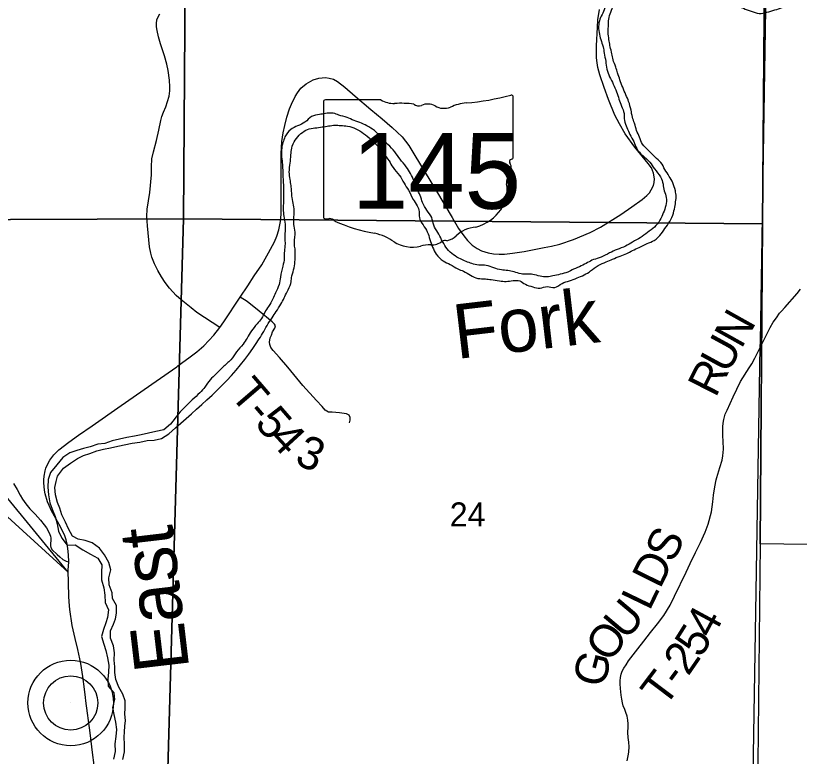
# Model space of a CAD drawing. Extents: x 0 to 34, y 0 to 22.
# Drawn here: x 5.171 to 6.533, y 17.465 to 18.753 of the extents above; entities that cross this region are included whole.
import ezdxf

# ---------------------------------------------------------------- set-up
doc = ezdxf.new("R2010")
doc.units = 0
for name, color, linetype in [('GM_X_Corporation', 7, 'Continuous'), ('GM_X_Major_River', 7, 'Continuous'), ('GM_X_Major_River_Text', 7, 'Continuous'), ('GM_X_Section_Text', 7, 'Continuous'), ('GM_X_State_Location', 7, 'Continuous'), ('GM_X_State_Route', 7, 'Continuous'), ('GM_X_State_Shield', 7, 'Continuous'), ('GM_X_Township_Road', 7, 'Continuous'), ('GM_X_Township_Road_Text', 7, 'Continuous'), ('GM_X_Township_Text', 7, 'Continuous'), ('GM_X_Unincorporated', 7, 'Continuous'), ('GM_X_Unincorporated_Location', 7, 'Continuous'), ('SH_Text', 7, 'Continuous')]:
    doc.layers.add(name, color=color, linetype=linetype)

msp = doc.modelspace()

# ---------------------------------------------------------------- linework, layer by layer
at = {"layer": 'GM_X_Corporation'}
for points in [[(5.4696, 19.395), (5.4623, 18.3997), (4.4097, 18.3961), (4.4084, 19.4053)], [(6.4758, 19.3912), (6.4726, 18.8257), (6.4692, 18.391), (5.4623, 18.3997), (5.4696, 19.395)], [(7.3418, 18.8315), (7.332, 17.8222), (6.4651, 17.8343), (6.4692, 18.391), (6.4726, 18.8257)], [(4.4097, 18.3961), (5.4623, 18.3997), (5.4343, 17.4017), (4.3969, 17.419)], [(6.4692, 18.391), (6.4651, 17.8343), (6.4606, 17.3985), (5.4343, 17.4017), (5.4623, 18.3997)]]:
    msp.add_lwpolyline(points, close=True, dxfattribs=at)
at = {"layer": 'GM_X_Major_River'}
for points in [[(5.4539, 18.0609), (5.44, 18.0428), (5.4281, 18.0331), (5.4145, 18.0302), (5.402, 18.0273), (5.3888, 18.0244), (5.3771, 18.0219), (5.3639, 18.0197), (5.3514, 18.0168), (5.3386, 18.0139), (5.3258, 18.0091), (5.3137, 18.0081), (5.3005, 18.0033), (5.2888, 18.0004), (5.2771, 17.9968), (5.2647, 17.9928), (5.2527, 17.9846), (5.2423, 17.9719), (5.2312, 17.9587), (5.2273, 17.9462), (5.2268, 17.9333), (5.2278, 17.9196), (5.2303, 17.906), (5.2344, 17.8947), (5.2395, 17.8823), (5.2428, 17.8695), (5.2453, 17.8566), (5.2509, 17.8442), (5.2606, 17.8323), (5.2742, 17.8325), (5.2877, 17.8241), (5.3007, 17.8167), (5.3137, 17.8098), (5.3204, 17.7981), (5.3203, 17.7845), (5.3202, 17.7716), (5.3239, 17.758), (5.3256, 17.7451), (5.3266, 17.7323), (5.3322, 17.7195), (5.3306, 17.7065), (5.3273, 17.697), (5.3234, 17.6852), (5.3198, 17.673), (5.3243, 17.6602), (5.3275, 17.6488), (5.3304, 17.636), (5.3326, 17.6235), (5.332, 17.6114), (5.3311, 17.5988), (5.3318, 17.5871), (5.3415, 17.5755), (5.3425, 17.5634), (5.3389, 17.5497), (5.3414, 17.5376), (5.3444, 17.5244), (5.3461, 17.5115), (5.3448, 17.4994), (5.3432, 17.4868), (5.3438, 17.4732), (5.3411, 17.4598)], [(5.357, 17.4594), (5.3598, 17.4727), (5.3599, 17.4852), (5.3593, 17.4981), (5.3602, 17.5076), (5.3608, 17.5175), (5.3617, 17.527), (5.3604, 17.538), (5.3613, 17.5494), (5.3611, 17.5611), (5.357, 17.5732), (5.35, 17.5852), (5.3452, 17.5987), (5.3434, 17.6105), (5.3432, 17.6203), (5.3422, 17.6324), (5.3428, 17.6446), (5.3406, 17.6571), (5.3358, 17.6702), (5.3356, 17.6831), (5.3406, 17.6946), (5.3446, 17.7042), (5.3463, 17.7141), (5.3461, 17.727), (5.339, 17.7393), (5.3384, 17.7492), (5.3336, 17.7631), (5.333, 17.7752), (5.3365, 17.7893), (5.3325, 17.8022), (5.325, 17.8153), (5.3164, 17.8269), (5.3038, 17.8361), (5.2915, 17.8401), (5.2794, 17.8425), (5.2698, 17.8476), (5.2627, 17.8604), (5.2576, 17.872), (5.2512, 17.8852), (5.2476, 17.8965), (5.2436, 17.9063), (5.2399, 17.9199), (5.2389, 17.9327), (5.241, 17.943), (5.2438, 17.9525), (5.2542, 17.966), (5.2662, 17.975), (5.2785, 17.9832), (5.2887, 17.9879), (5.2999, 17.9919), (5.312, 17.996), (5.3233, 17.9992), (5.3358, 18.0017), (5.3486, 18.0043), (5.3732, 18.0097), (5.3864, 18.0114), (5.3996, 18.0143), (5.4117, 18.015), (5.4242, 18.0179), (5.4369, 18.0257), (5.4488, 18.0365)]]:
    msp.add_lwpolyline(points, dxfattribs=at)
for points in [[(6.7856, 19.0726), (6.796, 19.0607), (6.8065, 19.0483), (6.8132, 19.0355), (6.8153, 19.0219), (6.814, 19.0097), (6.8104, 18.9971), (6.8034, 18.9845), (6.7934, 18.9714), (6.7815, 18.9602), (6.7684, 18.9474), (6.7553, 18.9358), (6.7456, 18.9272), (6.734, 18.9168), (6.7225, 18.9052), (6.7105, 18.8951), (6.6974, 18.8869), (6.6843, 18.8783), (6.6711, 18.8705), (6.6587, 18.865), (6.6463, 18.8598), (6.6334, 18.8577), (6.6187, 18.8529), (6.6059, 18.85), (6.5941, 18.8479), (6.5817, 18.8458), (6.5688, 18.8425), (6.5571, 18.8374), (6.5436, 18.8284), (6.5332, 18.8176), (6.5209, 18.8052), (6.5082, 18.7948), (6.4951, 18.7824), (6.4831, 18.7738), (6.4699, 18.7728), (6.4573, 18.776), (6.4436, 18.7781), (6.4306, 18.7832), (6.418, 18.7905), (6.4054, 18.796), (6.3927, 18.8042), (6.3812, 18.8112), (6.369, 18.8163), (6.3557, 18.8179), (6.3462, 18.8182), (6.3329, 18.8202), (6.3184, 18.8219), (6.304, 18.8246), (6.291, 18.829), (6.2792, 18.8307), (6.2671, 18.832), (6.2553, 18.8295), (6.2456, 18.8248), (6.2343, 18.8193), (6.2227, 18.8092), (6.2142, 18.7973), (6.2064, 18.7876), (6.1979, 18.7738), (6.1928, 18.7604), (6.1877, 18.7501), (6.1845, 18.7379), (6.1851, 18.7242), (6.188, 18.7117), (6.192, 18.6993), (6.1941, 18.6879), (6.1966, 18.6739), (6.1987, 18.6603), (6.2035, 18.6471), (6.2098, 18.6342), (6.2153, 18.6211), (6.2197, 18.6082), (6.2241, 18.5961), (6.2285, 18.5833), (6.2291, 18.5712), (6.2335, 18.5587), (6.2386, 18.5466), (6.2453, 18.5342), (6.2505, 18.5222), (6.2609, 18.5098), (6.2732, 18.4986), (6.2814, 18.4866), (6.2919, 18.4727), (6.2963, 18.4603), (6.2984, 18.4485), (6.302, 18.4372), (6.3011, 18.4231), (6.2968, 18.4102), (6.2909, 18.3975), (6.2813, 18.3856), (6.2693, 18.3759), (6.2566, 18.3669), (6.2434, 18.3595), (6.231, 18.3524), (6.2163, 18.3465), (6.2032, 18.3405), (6.1885, 18.3331), (6.1753, 18.3291)], [(6.2087, 18.3296), (6.2215, 18.3352), (6.2331, 18.3395), (6.2433, 18.3447), (6.255, 18.3502), (6.2685, 18.3569), (6.2809, 18.3624), (6.2932, 18.374), (6.3018, 18.3859), (6.3099, 18.3986), (6.3153, 18.4139), (6.3177, 18.4261), (6.319, 18.4386), (6.3177, 18.4489), (6.3133, 18.4625), (6.3071, 18.4738), (6.2996, 18.4858), (6.2926, 18.4978), (6.2826, 18.5071), (6.2718, 18.5183), (6.2606, 18.5299), (6.2554, 18.542), (6.2503, 18.5537), (6.2467, 18.5661), (6.2431, 18.5767), (6.2406, 18.5892), (6.2365, 18.6039), (6.2318, 18.6156), (6.2262, 18.6288), (6.2214, 18.6417), (6.2174, 18.6537), (6.2142, 18.6639), (6.2094, 18.6768), (6.2074, 18.687), (6.2045, 18.6991), (6.2028, 18.7089), (6.2011, 18.7211), (6.2012, 18.7347), (6.2018, 18.7473), (6.2057, 18.7595), (6.2108, 18.7725), (6.2193, 18.786), (6.2282, 18.7979), (6.2394, 18.8083), (6.2518, 18.8154), (6.2635, 18.8186), (6.2764, 18.8173), (6.2882, 18.8134), (6.302, 18.8083), (6.3142, 18.8047), (6.3275, 18.8023), (6.3378, 18.8017), (6.351, 18.8011), (6.3647, 18.7983), (6.375, 18.797), (6.3884, 18.7927), (6.4006, 18.7861), (6.4125, 18.7798), (6.424, 18.7728), (6.4359, 18.7662), (6.4496, 18.7611), (6.4633, 18.7571), (6.4766, 18.7593), (6.4905, 18.7633), (6.5037, 18.7677), (6.5168, 18.7774), (6.5272, 18.7902), (6.538, 18.8036), (6.5476, 18.8167), (6.5615, 18.8253), (6.5865, 18.8288), (6.602, 18.834), (6.6152, 18.8376), (6.6288, 18.842), (6.6389, 18.8464), (6.6529, 18.8501), (6.6631, 18.8533), (6.6763, 18.8588), (6.689, 18.8655), (6.7014, 18.8733), (6.7153, 18.8819), (6.7277, 18.8912), (6.7362, 18.9009), (6.7493, 18.9125), (6.7616, 18.9226), (6.7751, 18.9354), (6.7874, 18.947), (6.7989, 18.9589), (6.809, 18.9716), (6.8163, 18.9851), (6.8229, 18.9981), (6.8265, 19.0099), (6.827, 19.0228), (6.8245, 19.0357), (6.819, 19.0485), (6.812, 19.0602), (6.8019, 19.0722)], [(6.1753, 18.3291), (6.1651, 18.3239), (6.1542, 18.3181), (6.1407, 18.3121), (6.1305, 18.3074), (6.1177, 18.3034), (6.1049, 18.3005), (6.0946, 18.2988), (6.0825, 18.3001), (6.0699, 18.3033), (6.0604, 18.3039), (6.0494, 18.3041), (6.0376, 18.3077), (6.0262, 18.3098), (6.0152, 18.3111), (6.0022, 18.3147), (5.9888, 18.319), (5.9759, 18.3195), (5.9638, 18.322), (5.9542, 18.3256), (5.9289, 18.3396), (5.9189, 18.3504), (5.9114, 18.3636), (5.9048, 18.376), (5.8977, 18.3888), (5.8941, 18.402), (5.8859, 18.4148), (5.8781, 18.4283), (5.8741, 18.4404), (5.8685, 18.4525), (5.8634, 18.4657), (5.8575, 18.4785), (5.8497, 18.4905), (5.8392, 18.5036), (5.8299, 18.5164), (5.8179, 18.5291), (5.8079, 18.538), (5.7974, 18.5508), (5.7847, 18.5597), (5.7721, 18.5663), (5.7591, 18.571), (5.7469, 18.5761), (5.7328, 18.5804), (5.7229, 18.5836), (5.7092, 18.583), (5.699, 18.5813), (5.6854, 18.5777), (5.6738, 18.568), (5.661, 18.5617), (5.649, 18.5554), (5.639, 18.5423), (5.6354, 18.5328), (5.6329, 18.5198), (5.6332, 18.5073), (5.6345, 18.4944), (5.6351, 18.4819), (5.6357, 18.469), (5.6363, 18.4564), (5.6362, 18.4443), (5.6364, 18.4298), (5.6359, 18.4169), (5.6372, 18.4044), (5.6394, 18.3908), (5.6392, 18.3779), (5.6387, 18.3657), (5.6392, 18.3562), (5.6379, 18.3437), (5.6377, 18.3311), (5.6353, 18.3178), (5.6311, 18.2987), (5.6287, 18.2854), (5.6225, 18.2712), (5.6181, 18.2605), (5.6104, 18.2475), (5.6037, 18.2371), (5.5982, 18.2268), (5.5904, 18.2171), (5.5808, 18.2048), (5.573, 18.1925), (5.5664, 18.1821), (5.5549, 18.1686), (5.5449, 18.1548), (5.531, 18.1417), (5.5195, 18.1301), (5.5087, 18.12), (5.4998, 18.1073), (5.4908, 18.0973), (5.4778, 18.0849), (5.4662, 18.0737), (5.4539, 18.0609)], [(5.4488, 18.0365), (5.5832, 18.1745), (5.5921, 18.1879), (5.6002, 18.2006), (5.6079, 18.2144), (5.6168, 18.2278), (5.6238, 18.2386), (5.6319, 18.2516), (5.6429, 18.2731), (5.6491, 18.2876), (5.6505, 18.2975), (5.654, 18.3109), (5.6564, 18.3254), (5.6566, 18.3356), (5.6569, 18.3451), (5.6555, 18.355), (5.6561, 18.3668), (5.6567, 18.3766), (5.6545, 18.3903), (5.6544, 18.4013), (5.6549, 18.4108), (5.654, 18.4237), (5.6515, 18.4369), (5.6505, 18.4476), (5.6496, 18.4578), (5.6479, 18.4684), (5.6465, 18.4813), (5.6481, 18.4969), (5.6494, 18.511), (5.6507, 18.5228), (5.6569, 18.5369), (5.6666, 18.5481), (5.6782, 18.5555), (5.6911, 18.558), (5.7039, 18.5598), (5.7149, 18.5615), (5.7263, 18.5628), (5.7358, 18.5622), (5.7479, 18.5613), (5.7624, 18.5566), (5.7755, 18.5485), (5.7885, 18.5381), (5.799, 18.5276), (5.8094, 18.5145), (5.8199, 18.501), (5.8269, 18.489), (5.8382, 18.4755), (5.846, 18.462), (5.8538, 18.4496), (5.8617, 18.4338), (5.8687, 18.4225), (5.8723, 18.4127), (5.8728, 18.402), (5.8791, 18.3892), (5.8865, 18.3772), (5.8909, 18.364), (5.8957, 18.3508), (5.902, 18.3384), (5.914, 18.3268), (5.9262, 18.3206), (5.9396, 18.3128), (5.9492, 18.3088), (5.9744, 18.2963), (5.9874, 18.2954), (5.9976, 18.2941), (6.0117, 18.292), (6.0235, 18.2911), (6.0356, 18.2924), (6.0474, 18.2919), (6.0569, 18.286), (6.0699, 18.2816), (6.0825, 18.2792), (6.0949, 18.2821), (6.1079, 18.2804), (6.121, 18.2875), (6.1335, 18.2919), (6.147, 18.297), (6.1703, 18.3092), (6.1834, 18.3189), (6.1974, 18.3249), (6.2087, 18.3296)]]:
    msp.add_spline(points, degree=3, dxfattribs=at)
at = {"layer": 'GM_X_State_Route'}
for points in [[(5.453, 18.1443), (5.4591, 18.1488), (5.4743, 18.1599), (5.4857, 18.1688), (5.4979, 18.1792), (5.5153, 18.1975), (5.5255, 18.2106), (5.5329, 18.2209), (5.5613, 18.2636), (5.5742, 18.2833), (5.5856, 18.3008), (5.5985, 18.3201), (5.6106, 18.3408), (5.6208, 18.3599), (5.6249, 18.3699), (5.6285, 18.381), (5.6312, 18.3953), (5.6323, 18.4079), (5.6321, 18.4211), (5.6324, 18.4389), (5.6321, 18.4835), (5.6321, 18.4978), (5.6324, 18.5133), (5.6338, 18.5343), (5.6358, 18.5495), (5.6385, 18.5622), (5.6424, 18.5768), (5.6471, 18.591), (5.6504, 18.5995), (5.6569, 18.613), (5.6605, 18.6189), (5.6665, 18.627), (5.6756, 18.6348), (5.6878, 18.642), (5.698, 18.6448), (5.7094, 18.6457), (5.7159, 18.6449), (5.7233, 18.6427), (5.7305, 18.6386), (5.7432, 18.6291), (5.7609, 18.6132), (5.7883, 18.5901), (5.8079, 18.5739), (5.8253, 18.559), (5.8425, 18.5423), (5.8543, 18.5273), (5.865, 18.5102), (5.8811, 18.4833), (5.9022, 18.4482), (5.9294, 18.4022), (5.9407, 18.3829), (5.9497, 18.3702), (5.9562, 18.362), (5.9646, 18.3542), (5.9732, 18.3484), (5.9809, 18.3444), (5.9924, 18.3405), (6.0018, 18.339), (6.0112, 18.3383), (6.0209, 18.3384), (6.0343, 18.3399), (6.0549, 18.3431), (6.0898, 18.3498), (6.1025, 18.3521), (6.1168, 18.3556), (6.1407, 18.3638), (6.1697, 18.3759), (6.1876, 18.3853), (6.2227, 18.4077), (6.2421, 18.4207), (6.2602, 18.4335), (6.2682, 18.4406), (6.2725, 18.4452), (6.2756, 18.4501), (6.2795, 18.4577), (6.2808, 18.4633), (6.2813, 18.4695), (6.28, 18.4793), (6.2761, 18.4886), (6.2706, 18.4964), (6.2472, 18.5246), (6.2302, 18.5478), (6.2204, 18.565), (6.2127, 18.5804), (6.2017, 18.6075), (6.1938, 18.6286), (6.1866, 18.6504), (6.183, 18.6633), (6.1816, 18.6712), (6.1806, 18.68), (6.1806, 18.687), (6.1808, 18.7011), (6.1821, 18.7336), (6.1831, 18.7459), (6.1859, 18.7643)], [(5.2436, 17.9959), (5.2457, 17.998), (5.263, 18.0111), (5.2801, 18.0235), (5.3039, 18.04), (5.3542, 18.0752), (5.415, 18.1174), (5.4507, 18.1426), (5.453, 18.1443)], [(5.3075, 17.4494), (5.3046, 17.4715), (5.3002, 17.5057), (5.2926, 17.5616), (5.2921, 17.5674), (5.2904, 17.5818), (5.2877, 17.6036), (5.284, 17.6263), (5.2789, 17.6508), (5.2742, 17.6696), (5.2693, 17.6927), (5.265, 17.7205), (5.2639, 17.7334), (5.2635, 17.7436), (5.2622, 17.7886), (5.263, 17.8034), (5.2624, 17.8151), (5.2616, 17.8262), (5.2602, 17.8339), (5.2583, 17.8413), (5.256, 17.8483), (5.2487, 17.8642), (5.2331, 17.892), (5.2288, 17.9014), (5.2263, 17.9078), (5.2223, 17.9213), (5.221, 17.9277), (5.2201, 17.9341), (5.2197, 17.9405), (5.2198, 17.9457), (5.2204, 17.952), (5.222, 17.9614), (5.2234, 17.9661), (5.2258, 17.9715), (5.2302, 17.98), (5.2371, 17.9894), (5.2436, 17.9959)]]:
    msp.add_lwpolyline(points, dxfattribs=at)
at = {"layer": 'GM_X_State_Shield'}
for p, q in [((6.0357, 18.5072), (6.0357, 18.6118)), ((5.7061, 18.6034), (5.7061, 18.4033)), ((5.8059, 18.6069), (5.7094, 18.6069)), ((6.0357, 18.5072), (6.0357, 18.5072))]:
    msp.add_line(p, q, dxfattribs=at)
for centre, major_axis, start_param, end_param in [((5.9183, 18.8797), (0.3495, 0), 4.814394, 5.042369), ((6.0321, 18.6123), (0.00367, 0), 6.141152, 7.989035), ((5.7099, 18.6039), (0.00382, 0), 1.712693, 3.28349), ((5.8289, 18.6301), (0.037, 0), 4.042523, 4.731795), ((5.8412, 18.4945), (0.133, 0), 1.404758, 1.657858), ((5.8713, 18.6049), (0.0107, 0), 3.836095, 5.185415), ((5.887, 18.5818), (0.0222, 0), 0.950623, 2.079405), ((5.9629, 18.5458), (0.0703, 0), 1.699011, 2.107814), ((5.9157, 18.6135), (0.0267, 0), 4.081561, 5.145723), ((6.0349, 18.4995), (0.00568, 0), 1.883978, 3.671073), ((6.0318, 18.5067), (0.00393, 0), 5.05454, 6.418171), ((5.9987, 18.4862), (0.0341, 0), 5.934695, 6.695948), ((6.0489, 18.4633), (0.0248, 0), 2.387724, 3.262537), ((5.9379, 18.45), (0.0874, 0), 5.101752, 6.440018), ((5.7099, 18.4029), (0.00385, 0), 3.00124, 4.508301), ((5.7105, 18.4234), (0.0294, 0), 4.665946, 4.897461), ((5.7165, 18.3918), (0.0106, 0), 0.519207, 1.627899), ((5.8504, 18.5716), (0.2524, 0), 4.195997, 4.488961), ((5.9747, 18.3471), (0.0479, 0), 1.647645, 2.488434), ((5.7751, 18.3134), (0.079, 0), 0.823519, 1.323587), ((5.9141, 18.3839), (0.0282, 0), 4.937069, 5.64225), ((5.8605, 18.3908), (0.0501, 0), 4.026481, 4.996735), ((5.8895, 18.3216), (0.0412, 0), 1.495662, 1.94098), ((5.8931, 18.3758), (0.0267, 0), 4.691044, 5.507374), ((5.9173, 18.3564), (0.00752, 0), 1.147584, 2.315152)]:
    msp.add_ellipse(centre, major_axis=major_axis, ratio=0.8, start_param=start_param, end_param=end_param, dxfattribs=at)
at = {"layer": 'GM_X_Township_Road'}
for points in [[(5.5255, 18.2106), (5.4859, 18.2372), (5.476, 18.2448), (5.4614, 18.2564), (5.4546, 18.2622), (5.4499, 18.2667), (5.4382, 18.2794), (5.4308, 18.2892), (5.4242, 18.2988), (5.4178, 18.31), (5.4121, 18.3218), (5.4076, 18.3333), (5.4055, 18.3401), (5.4033, 18.3512), (5.4, 18.3878), (5.3991, 18.4039), (5.3996, 18.4165), (5.404, 18.4458), (5.4067, 18.4767), (5.407, 18.4904), (5.4077, 18.5043), (5.4102, 18.5164), (5.4157, 18.5361), (5.4196, 18.5543), (5.4231, 18.5708), (5.425, 18.578), (5.4279, 18.5857), (5.4316, 18.5949), (5.435, 18.6042), (5.4376, 18.6133), (5.4387, 18.6224), (5.4391, 18.6296), (5.4385, 18.6412), (5.4359, 18.6579), (5.4334, 18.6691), (5.4293, 18.6836), (5.4223, 18.7041), (5.4191, 18.7167), (5.4166, 18.7276), (5.4157, 18.7342), (5.4156, 18.7395), (5.4163, 18.7461), (5.4177, 18.7504), (5.4212, 18.7565)], [(6.5024, 18.2394), (6.5078, 18.2455), (6.5293, 18.2701), (6.5354, 18.2774)], [(5.7513, 18.0452), (5.7521, 18.0494), (5.7522, 18.0545), (5.7508, 18.0582), (5.7462, 18.0606), (5.7336, 18.0623), (5.7212, 18.0633), (5.7147, 18.0633), (5.7091, 18.0673), (5.7037, 18.0733), (5.6939, 18.0838), (5.6702, 18.1099), (5.644, 18.1418), (5.6297, 18.1586), (5.6184, 18.1706), (5.6144, 18.176), (5.6124, 18.1811), (5.6119, 18.1852), (5.6135, 18.1929), (5.6155, 18.1978), (5.6175, 18.2034), (5.6213, 18.2095), (5.6223, 18.214), (5.6206, 18.2168), (5.6168, 18.2207), (5.5944, 18.2391), (5.5731, 18.2558), (5.5613, 18.2636)], [(6.2338, 17.4568), (6.2365, 17.4685), (6.237, 17.4726), (6.2374, 17.4812), (6.2367, 17.4892), (6.2354, 17.4978), (6.2351, 17.5063), (6.2355, 17.5163), (6.2359, 17.5212), (6.2351, 17.5279), (6.2338, 17.5348), (6.2318, 17.5409), (6.2297, 17.546), (6.2272, 17.5526), (6.2258, 17.5579), (6.2245, 17.5643), (6.2234, 17.5711), (6.2229, 17.5768), (6.2223, 17.5828), (6.222, 17.5907), (6.222, 17.5964), (6.2225, 17.6018), (6.2234, 17.6075), (6.2253, 17.6127), (6.2281, 17.6181), (6.2321, 17.6242), (6.2363, 17.6307), (6.2526, 17.6519), (6.2628, 17.6653), (6.2745, 17.6803), (6.2869, 17.6955), (6.2975, 17.7101), (6.3086, 17.7278), (6.316, 17.7433), (6.3363, 17.7853), (6.3434, 17.8004), (6.3527, 17.8196), (6.3616, 17.8368), (6.3697, 17.8546), (6.375, 17.8685), (6.3804, 17.8902), (6.3827, 17.9073), (6.3841, 17.919), (6.3862, 17.9336), (6.3887, 17.9461), (6.3897, 17.9499), (6.3948, 17.9674), (6.3991, 17.9803), (6.4005, 17.9874), (6.4012, 17.9992), (6.4011, 18.013), (6.4005, 18.0223), (6.4, 18.0323), (6.4002, 18.0383), (6.401, 18.0442), (6.4018, 18.0506), (6.4031, 18.0554), (6.4045, 18.0602), (6.4078, 18.0673), (6.4182, 18.09), (6.4311, 18.1167), (6.4461, 18.1408), (6.4504, 18.1478), (6.4558, 18.1574), (6.4655, 18.1772), (6.4825, 18.2106), (6.488, 18.2201), (6.4933, 18.2279), (6.499, 18.2356), (6.5024, 18.2394)], [(5.1672, 17.9392), (5.1732, 17.9292), (5.1784, 17.9189), (5.1825, 17.9121), (5.1886, 17.9038), (5.1955, 17.8956), (5.2044, 17.8862), (5.2142, 17.8756), (5.2206, 17.8677), (5.2241, 17.8622), (5.2288, 17.8537), (5.2313, 17.8479), (5.2321, 17.8441), (5.2312, 17.8313), (5.232, 17.8283), (5.2342, 17.8238), (5.2432, 17.816), (5.2478, 17.8116), (5.2529, 17.8071), (5.2584, 17.8046), (5.263, 17.8034)]]:
    msp.add_lwpolyline(points, dxfattribs=at)
at = {"layer": 'GM_X_Township_Text'}
msp.add_lwpolyline([(6.4525, 17.3965), (6.4653, 18.1777), (6.4655, 18.1862), (6.4767, 18.8745), (6.4767, 18.8755), (6.4827, 20.9), (2.1, 20.9), (2.1, 19.4241)], dxfattribs=at)
at = {"layer": 'GM_X_Unincorporated'}
for radius in [0.0744, 0.0472]:
    msp.add_circle((5.2665, 17.5577), radius, dxfattribs=at)
at = {"layer": 'GM_X_Unincorporated_Location'}
msp.add_line((5.2665, 17.5577), (5.2665, 17.5577), dxfattribs=at)
at = {"layer": 'SH_Text'}
msp.add_lwpolyline([(5.2622, 17.7854), (4.4854, 18.7335), (4.4854, 18.4935)], close=True, dxfattribs=at)

# ---------------------------------------------------------------- texts
at = {"layer": 'GM_X_Major_River_Text'}
for s, rotation, p in [('Fork', 6.7255, (5.9374, 18.1559)), ('East', 96.7272, (5.4728, 17.6176))]:
    msp.add_text(s, height=0.09469, rotation=rotation, dxfattribs=at).set_placement(p)
at = {"layer": 'GM_X_Section_Text'}
msp.add_text('24', height=0.04186, rotation=0, dxfattribs=at).set_placement((5.9254, 17.8647))
at = {"layer": 'GM_X_State_Location'}
for s in ['s', 'r']:
    msp.add_text(s, height=0.000189, dxfattribs=at).set_placement((5.8672, 18.4901))
msp.add_text('145', height=0.000189, rotation=0, dxfattribs=at).set_placement((5.8004, 18.4763))
at = {"layer": 'GM_X_State_Shield'}
msp.add_text('145', height=0.13184, dxfattribs=at).set_placement((5.7553, 18.4174))
at = {"layer": 'GM_X_Township_Road_Text'}
for s, rotation, p in [('N', 60.7214, (6.4324, 18.1723)), ('U', 61.3264, (6.4085, 18.1286)), ('R', 63.2342, (6.3877, 18.0874)), ('T', 310.6534, (5.5416, 18.0933)), ('-', 310.6905, (5.5693, 18.061)), ('5', 310.8418, (5.5847, 18.0432)), ('4', 312.5472, (5.6088, 18.0153)), ('3', 336.7839, (5.6537, 17.9745)), ('S', 63.7332, (6.3133, 17.7994)), ('D', 63.6956, (6.2911, 17.7546)), ('L', 64.2399, (6.2727, 17.7164)), ('U', 49.8614, (6.232, 17.6652)), ('4', 61.68, (6.3819, 17.6674)), ('O', 53.8368, (6.2032, 17.6256)), ('5', 57.9623, (6.3614, 17.6343)), ('2', 55.4314, (6.34, 17.6031)), ('G', 75.8242, (6.1933, 17.5823)), ('T', 53.0264, (6.2991, 17.5483)), ('-', 53.6513, (6.325, 17.5828))]:
    msp.add_text(s, height=0.0568, rotation=rotation, dxfattribs=at).set_placement(p)

doc.saveas('drawing.dxf')
